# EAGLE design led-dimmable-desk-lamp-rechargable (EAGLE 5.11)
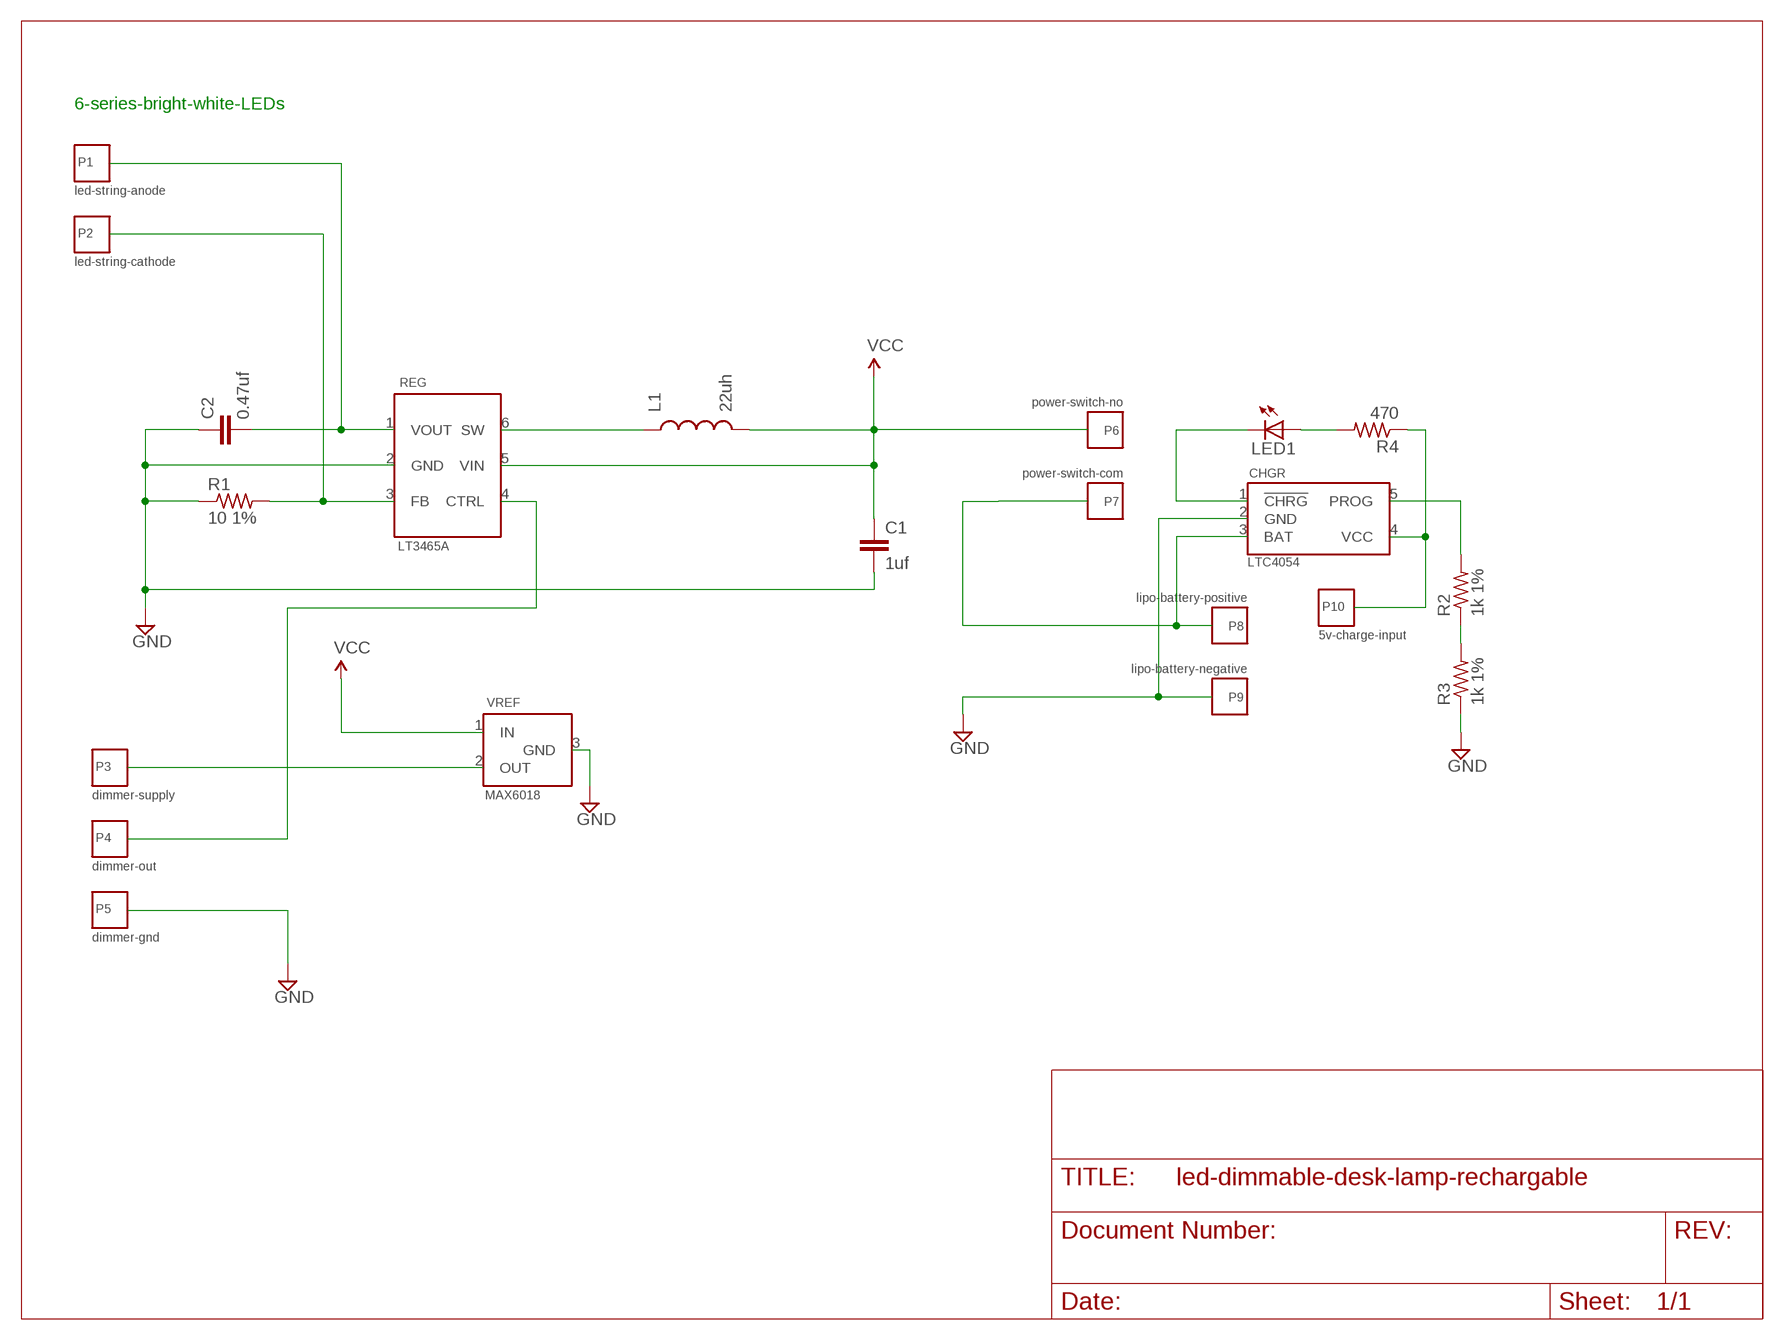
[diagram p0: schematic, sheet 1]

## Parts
C1  1uf  C-EUC1206  [C1206]
C2  0.47uf  C-EUC1206  [C1206]
CHGR  LTC4054  [TSOT23-5]
L1  22uh  INDUCTOR1210  [1210]
LED1  LED5MM  [LED5MM]
P1  led-string-anode  WIREPAD-SMD  [WIREPAD-SMD]
P2  led-string-cathode  WIREPAD-SMD  [WIREPAD-SMD]
P3  dimmer-supply  WIREPAD-SMD  [WIREPAD-SMD]
P4  dimmer-out  WIREPAD-SMD  [WIREPAD-SMD]
P5  dimmer-gnd  WIREPAD-SMD  [WIREPAD-SMD]
P6  power-switch-no  WIREPAD-SMD  [WIREPAD-SMD]
P7  power-switch-com  WIREPAD-SMD  [WIREPAD-SMD]
P8  lipo-battery-positive  WIREPAD-SMD  [WIREPAD-SMD]
P9  lipo-battery-negative  WIREPAD-SMD  [WIREPAD-SMD]
P10  5v-charge-input  WIREPAD-SMD  [WIREPAD-SMD]
R1  10 1%  R-US_R1210  [R1210]
R2  1k 1%  R-US_R1210  [R1210]
R3  1k 1%  R-US_R1210  [R1210]
R4  470  R-US_R1206  [R1206]
REG  LT3465A  [SOT23-6]
VREF  MAX6018  [SOT23-3]

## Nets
GND: C1.2 C2.1 CHGR.2(GND) P5.1(P) P9.1(P) R1.1 R3.1 REG.2(GND) VREF.3(GND)
N$1: L1.1 REG.6(SW)
N$2: C2.2 P1.1(P) REG.1(VOUT)
N$3: P3.1(P) VREF.2(OUT)
N$4: P2.1(P) R1.2 REG.3(FB)
N$5: P4.1(P) REG.4(CTRL)
N$6: CHGR.3(BAT) P7.1(P) P8.1(P)
N$7: CHGR.5(PROG) R2.2
N$8: CHGR.4(VCC) P10.1(P) R4.1
N$9: R2.1 R3.2
N$10: CHGR.1(!CHRG) LED1.K(C)
N$11: LED1.A R4.2
VCC: C1.1 L1.2 P6.1(P) REG.5(VIN) VREF.1(IN)

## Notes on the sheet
- 6-series-bright-white-LEDs

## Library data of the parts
C1 C2 = rcl:C-EU: CAPACITOR, European symbol
CHGR = trl:LTC4054
L1 = SparkFun:INDUCTOR: Inductors
LED1 = led:LED: LED
P1-P10 = trl:WIREPAD-SMD
R1-R4 = resistor:R-US_: RESISTOR, American symbol
REG = trl:LT3465A
VREF = trl:MAX6018

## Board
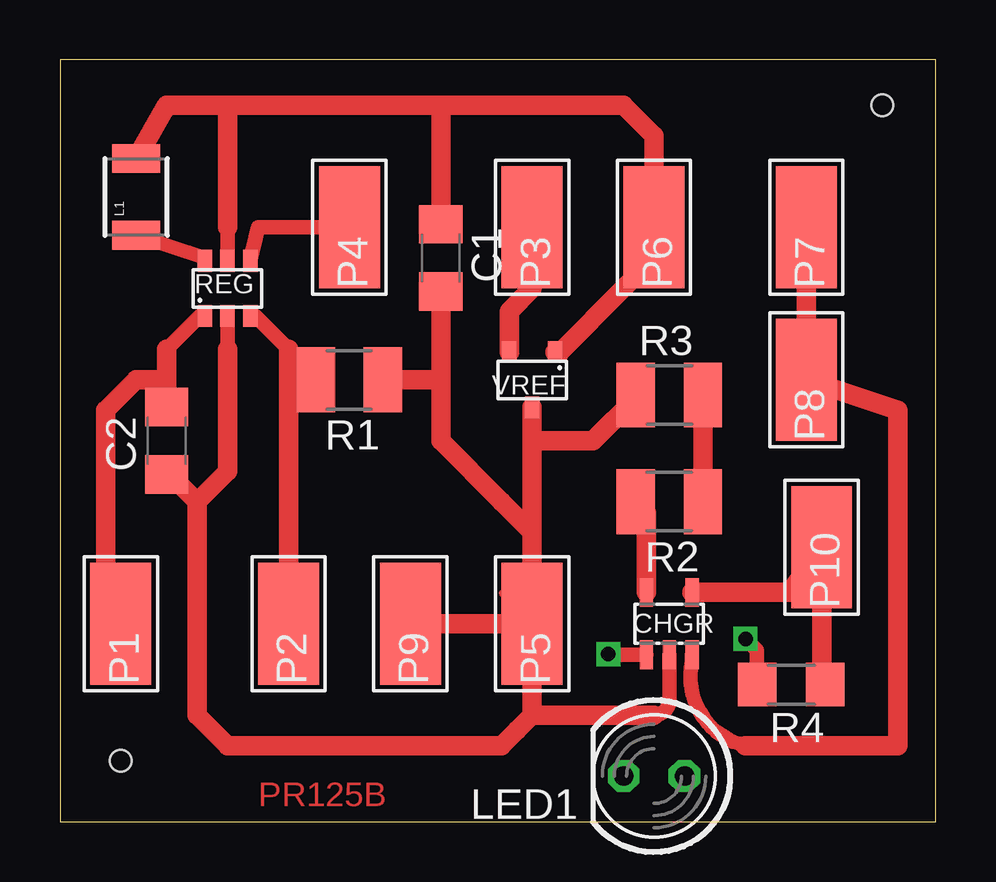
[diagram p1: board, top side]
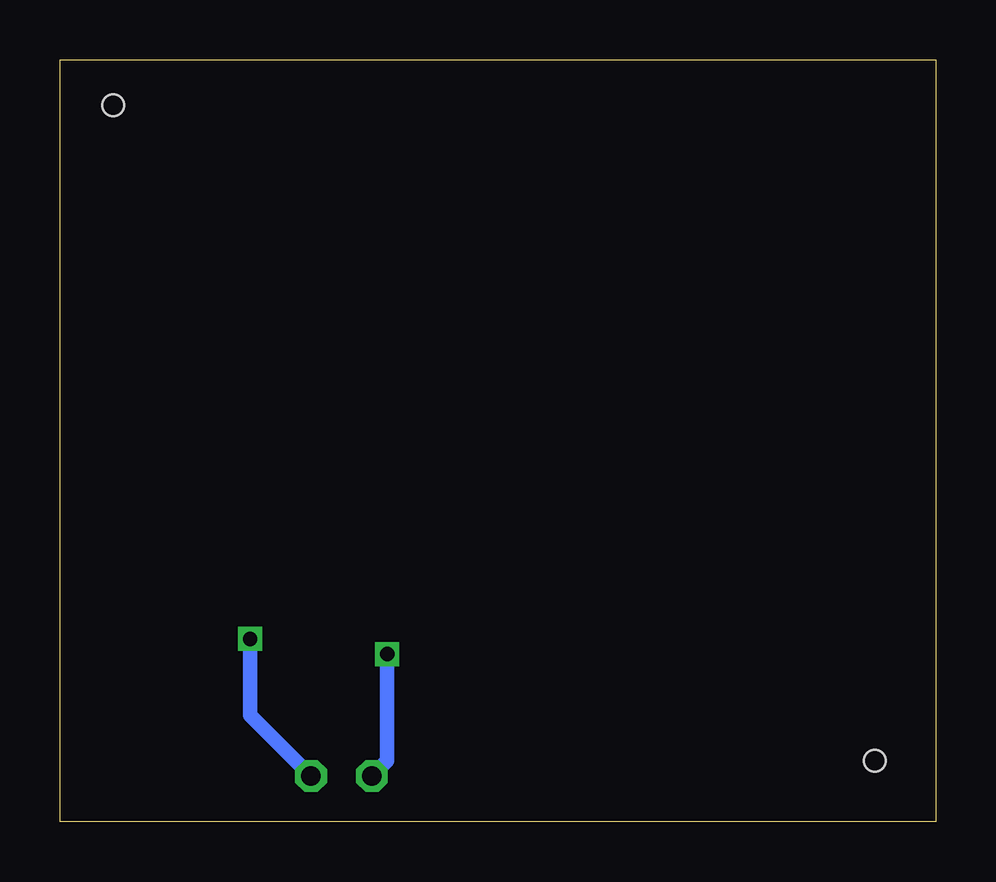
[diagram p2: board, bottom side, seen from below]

Size 36.5 x 31.74 mm. Coordinates in mm from the lower left corner, seen from the top.
Outline: 0,0 36.5,0 36.5,31.74 0,31.74 0,0
Copper layers (1*16): Top 0.035mm / dielectric 1.5mm / Bottom 0.035mm
Design rules "default": minimum track width 10mil, minimum drill 24mil, track to track 8mil, track to pad 8mil, pad to pad 8mil, via to via 8mil, smd to smd 8mil, copper to edge 40mil, drill to drill 8mil, minimum pad ring 10mil, minimum via ring 8mil, stop-mask expansion 4mil, vias tented up to drill 0mil, thermal gap 10mil
Holes 0.9 mm at 34.29,29.84 2.54,2.54

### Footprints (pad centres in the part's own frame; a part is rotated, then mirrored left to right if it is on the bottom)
C1206 = smd 1.6 x 1.8: 1 -1.4,0; 2 1.4,0
TSOT23-5 = smd 0.55 x 1.2: 1 -0.95,-1.3; 2 0,-1.3; 3 0.95,-1.3; 4 0.95,1.3; 5 -0.95,1.3
1210 = smd 1.2 x 2: 1 -1.6,0; 2 1.6,0
LED5MM = drill 0.813 octagon: A -1.27,0; K 1.27,0
WIREPAD-SMD = smd 2.54 x 5.08: 1 0,0
R1210 = smd 1.6 x 2.7: 1 -1.4,0; 2 1.4,0
R1206 = smd 1.6 x 1.803: 1 -1.422,0; 2 1.422,0
SOT23-6 = smd 0.6 x 0.9: 1 -0.95,-1.15; 2 0,-1.15; 3 0.95,-1.15; 4 0.95,1.15; 5 0,1.15; 6 -0.95,1.15
SOT23-3 = smd 0.6 x 0.9: 1 -0.95,-1.15; 2 0.95,-1.15; 3 0,1.15

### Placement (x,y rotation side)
C1  15.88,23.5 270 top
C2  4.45,15.88 90 top
CHGR  25.4,8.26 0 top
L1  3.17,26.04 90 top
LED1  24.77,1.91 180 top
P1  2.54,8.26 0 top
P2  9.53,8.26 0 top
P3  19.68,24.77 0 top
P4  12.06,24.77 0 top
P5  19.68,8.26 0 top
P6  24.77,24.77 0 top
P7  31.11,24.77 0 top
P8  31.11,18.41 0 top
P9  14.61,8.26 0 top
P10  31.75,11.43 0 top
R1  12.06,18.41 180 top
R2  25.4,13.34 180 top
R3  25.4,17.78 0 top
R4  30.48,5.71 180 top
REG  6.99,22.23 0 top
VREF  19.68,18.41 180 top

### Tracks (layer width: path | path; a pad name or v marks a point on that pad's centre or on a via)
GND
  Top 0.254: REG.2 6.99,20.95 | P5.1 18.41,9.53
  Top 0.61: 6.99,19.68 REG.2 | CHGR.2 25.4,5.08 arc-90 24.77,4.45
  Top 0.813: P5.1 P9.1 | 19.68,4.45 19.05,3.81 18.41,3.17 6.99,3.17 5.71,4.45 5.71,12.06 5.71,13.34 | 19.68,12.06 19.68,10.79 P5.1 | 19.68,12.06 18.41,13.34 15.88,15.88 15.88,17.14 15.88,18.41 | 15.88,18.41 15.88,20.95 15.88,22.23 C1.2 | 6.99,19.68 6.99,14.61 5.71,13.34 | 5.71,13.34 4.45,14.61 C2.1 | 19.68,4.45 P5.1 | 19.68,12.06 19.68,15.88 | 19.68,15.88 VREF.3 | 15.88,18.41 R1.1 | R3.1 24,17.65 22.23,15.88 19.68,15.88 | 19.68,4.45 24.77,4.45
N$1
  Top 0.406: REG.6 6.04,23.5
  Top 0.61: 6.04,23.5 L1.1
N$2
  Top 0.61: REG.1 5.83,21.07 4.45,19.68
  Top 0.813: 4.45,18.41 4.45,17.14 C2.2 | 4.45,18.41 4.45,19.68 | 4.45,18.41 3.17,18.41 1.91,17.14 1.91,9.53 1.91,8.89 P1.1
N$3
  Top 0.813: VREF.2 18.73,21.27 19.68,22.23 P3.1
N$4
  Top 0.61: REG.3 8.13,21.07 9.53,19.68
  Top 0.813: P2.1 9.53,18.41 | 9.53,18.41 9.53,19.68 | 9.53,18.41 R1.2
N$5
  Top 0.61: REG.4 8.26,24.77 P4.1
N$6
  Top 0.61: CHGR.3 26.35,6.67 arc90 28.57,3.17
  Top 0.813: P7.1 P8.1 34.92,17.14 34.92,3.17 28.57,3.17
N$7
  Top 0.813: CHGR.5 24.45,12.88 R2.2
N$8
  Top 0.813: CHGR.4 30.45,9.55 P10.1 31.75,5.71 R4.1
N$9
  Top 0.813: R2.1 R3.2
N$10  (via drill 0.6)
  Top 0.61: CHGR.1 22.89,6.96 v22.86,6.99
  Bottom 0.61: v22.86,6.99 22.86,2.54 LED1.K
N$11  (via drill 0.6)
  Top 0.61: R4.2 29.06,7.14 v28.57,7.62
  Bottom 0.61: v28.57,7.62 28.57,4.45 LED1.A
VCC
  Top 0.254: REG.5 6.99,23.5
  Top 0.61: 6.99,23.5 6.99,24.77
  Top 0.813: C1.1 15.88,29.84 14.61,29.84 | 6.99,29.84 4.45,29.84 L1.2 | 6.99,29.84 14.61,29.84 | 14.61,29.84 23.5,29.84 24.77,28.57 P6.1 24.77,23.5 23.5,22.23 20.84,19.57 VREF.1 | 6.99,24.77 6.99,29.84

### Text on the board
Top: PR125B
